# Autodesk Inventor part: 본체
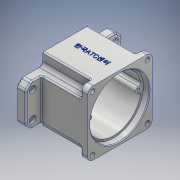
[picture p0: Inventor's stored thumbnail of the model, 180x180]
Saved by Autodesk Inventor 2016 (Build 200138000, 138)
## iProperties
Created: 2017-01
Part Number: 본체
Material: 알루미늄 6061
Document SubType Name: Modeling
Designer: Owner
Mass: 876.665 g
Surface Area: 765.409 cm^2
Volume: 324.691 cm^3
Density: 2.7 g/cm^3
Appearance: 알루미늄 - 평지
Author: Owner
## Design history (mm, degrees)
sketch "스케치1"
  geometry: L1 (-47, 47)-(47, 47); L2 (47, 47)-(47, -47); L3 (47, -47)-(-47, -47); L4 (-47, -47)-(-47, 47); L5 (-47, 47)-(47, -47); L6 (47, 47)-(-47, -47); 1 further point
  constraints: 12 end point, 2 midpoint, 2 parallel, 1 horizontal, 1 perpendicular
  dimensions: "d0" = 94 distance of L2.end L3.end; "d1" = 94 distance of L1.end L2.end
extrude "돌출1" new body sketch "스케치1" distance "d2" = 80; taper "d3" = 0 deg
sketch "스케치2"
  geometry: L1 (30, 70)-(-30, 70); L2 (-30, -70)-(30, -70); L3 (30, 70)-(-30, -70); L4 (-30, 70)-(30, -70); L5 (47, -33)-(47, 33); L6 (-47, 33)-(-47, -33); L7 (-47, -33)-(47, 33); L8 (47, -33)-(-47, 33); L9 (-47, -33)-(-30, -33); L10 (30, -33)-(47, -33); L11 (30, -70)-(30, -33); L12 (30, 33)-(30, 70); L13 (47, 33)-(30, 33); L14 (-30, 33)-(-47, 33); L15 (-30, 70)-(-30, 33); L16 (-30, -33)-(-30, -70); 9 further points
  constraints: 32 end point, 12 midpoint, 10 parallel, 4 perpendicular, 3 horizontal, 2 horizontal alignment, 2 vertical alignment
  dimensions: "d4" = 60 distance of L2.start L2.end; "d5" = 66 distance of L5.start L5.end; "d6" = 140 distance between parallel lines of L2 L1; "d7" = 94 distance between parallel lines of L6 L5
extrude "돌출2" join sketch "스케치2" distance "d8" = 13; taper "d9" = 0 deg
sketch "스케치3"
  geometry: L1 (47, -47)-(47, 47) reference; L2 (47, -47)-(30, -47); L3 (30, -47)-(30, -33); L4 (30, -33)-(47, -33); L5 (47, -33)-(47, -47); 1 further point
  constraints: 8 end point, 2 parallel, 1 horizontal, 1 perpendicular
  dimensions: "d10" = 17 distance of L3.end L4.end; "d11" = 14 distance of L2.end L3.end
extrude "돌출3" cut sketch "스케치3" distance "d12" = 70; taper "d13" = 0 deg
hole "구멍1" diameter "d32" = 80; stored, may be unused: countersink angle "d36" = 90 deg, drill point angle "d38" = 0 deg; dims "d30" = 47, "d31" = 47, "d33" = 6, "d34" = 4, "d35" = 2, "d37" = 71
hole "구멍2" diameter "d41" = 86; stored, may be unused: countersink angle "d45" = 90 deg, drill point angle "d47" = 0 deg; dims "d39" = 10, "d40" = 10, "d42" = 6, "d43" = 4, "d44" = 2, "d46" = 9
sketch "스케치8"
  geometry: A1 r 21 centre (-11, 0) between (7.984, 8.978) and (7.984, -8.978); A2 r 15 centre (20, 0) between (7.984, -8.978) and (7.984, 8.978); 1 further point
  constraints: 4 point on circle, 2 centre point, 2 horizontal alignment
  dimensions: "d48" = 42 diameter of A1; "d49" = 11 distance of point (0, 0) A1.centre; "d50" = 30 diameter of A2; "d51" = 20 distance of point (0, 0) A2.centre
extrude "돌출6" join sketch "스케치8" distance "d52" = 7; taper "d53" = 0 deg
hole "구멍3" diameter "d56" = 22; stored, may be unused: countersink angle "d60" = 90 deg, drill point angle "d62" = 0 deg; dims "d54" = 10, "d55" = 10, "d57" = 6, "d58" = 4, "d59" = 2, "d61" = 7
hole "구멍4" diameter "d65" = 19; stored, may be unused: countersink angle "d69" = 90 deg, drill point angle "d71" = 0 deg; dims "d63" = 10, "d64" = 10, "d66" = 6, "d67" = 4, "d68" = 2, "d70" = 1
hole "구멍5" diameter "d80" = 25; stored, may be unused: countersink angle "d84" = 90 deg, drill point angle "d86" = 0 deg; dims "d78" = 10, "d79" = 10, "d81" = 6, "d82" = 4, "d83" = 2, "d85" = 1
hole "구멍6" diameter "d89" = 35; stored, may be unused: countersink angle "d93" = 90 deg, drill point angle "d95" = 0 deg; dims "d87" = 10, "d88" = 10, "d90" = 6, "d91" = 4, "d92" = 2, "d94" = 10
sketch "스케치10"
  geometry: A1 r 4 centre (0, 36) between (-3.997, 35.852) and (3.997, 35.852); A2 r 40 centre (0, 0) between (8.214, 39.148) and (-8.214, 39.148) reference; A3 r 3.5 centre (-7.495, 35.722) between (-3.997, 35.852) and (-8.214, 39.148); A4 r 3.5 centre (7.495, 35.722) between (8.214, 39.148) and (3.997, 35.852); 1 further point
  constraints: 8 point on circle, 4 tangent, 3 centre point, 1 vertical alignment
  dimensions: "d105" = 8 diameter of A1; "d106" = 36 distance of A1.centre point (0, 0); "d107" = 7 diameter of A3; "d108" = 7 diameter of A4
extrude "돌출7" join sketch "스케치10" stored distance "d109" = 7; taper "d110" = 0 deg
hole "구멍8" diameter "d113" = 7; stored, may be unused: countersink angle "d117" = 90 deg, drill point angle "d119" = 0 deg; dims "d111" = 7, "d112" = 7, "d114" = 6, "d115" = 4, "d116" = 2, "d118" = 8
hole "구멍9" diameter "d122" = 4; stored, may be unused: countersink angle "d126" = 90 deg, drill point angle "d128" = 0 deg; dims "d120" = 11, "d121" = 10, "d123" = 6, "d124" = 10, "d125" = 4, "d127" = 8
hole "구멍10" diameter "d131" = 3.242; stored, may be unused: countersink angle "d135" = 90 deg, drill point angle "d137" = 118 deg; dims "d129" = 10, "d130" = 10, "d132" = 7, "d133" = 10, "d134" = 4, "d136" = 9
fillet "모깎기1" dims "d138" = 0.3
fillet "모깎기2" dims "d139" = 2
fillet "모깎기3" dims "d143" = 8
fillet "모깎기5" dims "d145" = 5
chamfer "모따기2" distance "d146" = 1; stored, may be unused: second distance "d147" = 2, angle "d148" = 45 deg
fillet "모깎기6" dims "d149" = 3
fillet "모깎기7" dims "d150" = 2
fillet "모깎기8" dims "d151" = 2
fillet "모깎기9" dims "d152" = 2
sketch "스케치11"
  geometry: L1 (0, 0)-(0, 78) reference; 3 further points
  constraints: 1 horizontal alignment, 1 midpoint, 1 other
  dimensions: "d154" = 40 distance of point (-40, 39) point (0, 39)
chamfer "모따기3" distance "d155" = 8; stored, may be unused: second distance "d156" = 2, angle "d157" = 45 deg
sketch "스케치12"
  geometry: C1 r 27.5 at (11, 0); C2 r 12.5 at (11, 0) reference; 1 further point
  constraints: 1 centre point, 1 coincident
  dimensions: "d158" = 55 diameter of C1
extrude "돌출8" join sketch "스케치12" distance "d159" = 7; taper "d160" = 0 deg
feature "엠보싱1" dims "d4" = 60, "d5" = 66, "d6" = 140, "d7" = 94, "d161" = 0.5, "d162" = 0
hole "구멍11" diameter "d165" = 32; stored, may be unused: countersink angle "d169" = 90 deg, drill point angle "d171" = 0 deg; dims "d163" = 10, "d164" = 10, "d166" = 7, "d167" = 10, "d168" = 4, "d170" = 8
fillet "모깎기11" dims "d172" = 5
fillet "모깎기12" dims "d173" = 2
sketch "스케치13"
  geometry: L1 (45, 33)-(35, 33) reference; L2 (30, 38)-(30, 59.929) reference; L3 (23.464, 68.536)-(28.536, 63.464) reference; L4 (19.929, 70)-(-19.929, 70) reference; L5 (-28.536, 63.464)-(-23.464, 68.536) reference; L6 (-30, 59.929)-(-30, 38) reference; L7 (-35, 33)-(-45, 33) reference; L8 (-47, 31)-(-47, -31) reference; L9 (-45, -33)-(-35, -33) reference; L10 (-30, -38)-(-30, -59.929) reference; L11 (-23.464, -68.536)-(-28.536, -63.464) reference; L12 (-19.929, -70)-(19.929, -70) reference; L13 (28.536, -63.464)-(23.464, -68.536) reference; L14 (30, -59.929)-(30, -38) reference; L15 (35, -33)-(45, -33) reference; L16 (47, -31)-(47, 31) reference; L17 (29, -38)-(29, -59.929); L18 (27.828, -62.757)-(22.757, -67.828); L19 (19.929, -69)-(-19.929, -69); L20 (-22.757, -67.828)-(-27.828, -62.757); L21 (-29, -59.929)-(-29, -38); L22 (-35, -32)-(-45, -32); L23 (-46, -31)-(-46, 31); L24 (-45, 32)-(-35, 32); L25 (-29, 38)-(-29, 59.929); L26 (-27.828, 62.757)-(-22.757, 67.828); L27 (-19.929, 69)-(19.929, 69); L28 (22.757, 67.828)-(27.828, 62.757); L29 (29, 59.929)-(29, 38); L30 (35, 32)-(45, 32); L31 (46, 31)-(46, -31); L32 (45, -32)-(35, -32); C1 r 27.5 at (11, 0) reference; C2 r 2 at (-19, 60) reference; C3 r 2 at (19, 60) reference; C4 r 2 at (-19, -60) reference; C5 r 2 at (19, -60) reference; A1 r 2 centre (45, 31) between (47, 31) and (45, 33) reference; A2 r 5 centre (35, 38) between (30, 38) and (35, 33) reference; A3 r 5 centre (25, 59.929) between (30, 59.929) and (28.536, 63.464) reference; A4 r 5 centre (19.929, 65) between (23.464, 68.536) and (19.929, 70) reference; A5 r 5 centre (-19.929, 65) between (-19.929, 70) and (-23.464, 68.536) reference; A6 r 5 centre (-25, 59.929) between (-28.536, 63.464) and (-30, 59.929) reference; A7 r 5 centre (-35, 38) between (-35, 33) and (-30, 38) reference; A8 r 2 centre (-45, 31) between (-45, 33) and (-47, 31) reference; A9 r 2 centre (-45, -31) between (-47, -31) and (-45, -33) reference; A10 r 5 centre (-35, -38) between (-30, -38) and (-35, -33) reference; A11 r 5 centre (-25, -59.929) between (-30, -59.929) and (-28.536, -63.464) reference; A12 r 5 centre (-19.929, -65) between (-23.464, -68.536) and (-19.929, -70) reference; A13 r 5 centre (19.929, -65) between (19.929, -70) and (23.464, -68.536) reference; A14 r 5 centre (25, -59.929) between (28.536, -63.464) and (30, -59.929) reference; A15 r 5 centre (35, -38) between (35, -33) and (30, -38) reference; A16 r 2 centre (45, -31) between (45, -33) and (47, -31) reference; A17 r 4 centre (25, -59.929) between (27.828, -62.757) and (29, -59.929); A18 r 4 centre (19.929, -65) between (19.929, -69) and (22.757, -67.828); A19 r 4 centre (-19.929, -65) between (-22.757, -67.828) and (-19.929, -69); A20 r 4 centre (-25, -59.929) between (-29, -59.929) and (-27.828, -62.757); A21 r 6 centre (-35, -38) between (-29, -38) and (-35, -32); A22 r 1 centre (-45, -31) between (-46, -31) and (-45, -32); A23 r 1 centre (-45, 31) between (-45, 32) and (-46, 31); A24 r 6 centre (-35, 38) between (-35, 32) and (-29, 38); A25 r 4 centre (-25, 59.929) between (-27.828, 62.757) and (-29, 59.929); A26 r 4 centre (-19.929, 65) between (-19.929, 69) and (-22.757, 67.828); A27 r 4 centre (19.929, 65) between (22.757, 67.828) and (19.929, 69); A28 r 4 centre (25, 59.929) between (29, 59.929) and (27.828, 62.757); A29 r 6 centre (35, 38) between (29, 38) and (35, 32); A30 r 1 centre (45, 31) between (46, 31) and (45, 32); A31 r 1 centre (45, -31) between (45, -32) and (46, -31); A32 r 6 centre (35, -38) between (35, -32) and (29, -38); 1 further point
  constraints: 32 end point, 32 point on circle, 16 centre point, 31 other
  dimensions: "d174" = 1 distance between parallel lines of L14 L17
extrude "돌출9" cut sketch "스케치13" distance "d175" = 1; taper "d176" = 0 deg
chamfer "모따기4" distance "d177" = 1; stored, may be unused: second distance "d178" = 2, angle "d179" = 45 deg
fillet "모깎기13" dims "d180" = 0.3
node "솔리드1"
mirror "대칭1"
mirror "대칭2"
mirror "대칭3"
mirror "대칭4"
mirror "대칭5"
mirror "대칭6"
mirror "대칭7"
mirror "대칭8"
node "투영된 루프2"
